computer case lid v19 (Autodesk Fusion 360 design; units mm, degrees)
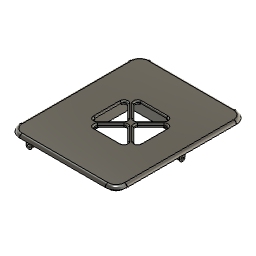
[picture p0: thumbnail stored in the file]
sketch "草图1" plane through (0, 0, 0) normal (0, 0, 1) x axis (1, 0, 0)
  line L1 (-5, 3.05) -> (-5, 81.95)
  line L2 (64.95, -5) -> (3.05, -5)
  line L3 (3.05, -3) -> (64.95, -3)
  line L4 (73, 81.95) -> (73, 3.05)
  line L5 (67.9994, 85) -> (0.0006, 85)
  line L6 (71, 3.05) -> (71, 81.95)
  line L7 (-3, 81.95) -> (-3, 3.05)
  line L8 (3.05, 90) -> (64.95, 90)
  line L9 (3.05, -1) -> (64.95, -1)
  line L10 (69, 3.05) -> (69, 81.95)
  line L11 (67.9994, 83) -> (0.0006, 83)
  line L12 (-1, 81.95) -> (-1, 3.05)
  line L13 (70.75, 3.05) -> (70.75, 81.95)
  line L14 (67.9994, 84.75) -> (0.0006, 84.75)
  line L15 (-2.75, 81.95) -> (-2.75, 3.05)
  line L16 (3.05, -2.75) -> (64.95, -2.75)
  arc A1 centre (0, 3.05) radius 3 clockwise from (-2.9993, 2.9875) to (-3, 3.05)
  arc A2 centre (68, 3.05) radius 3 clockwise from (71, 3.05) to (70.9993, 2.9875)
  arc A3 centre (0, 3.05) radius 5 clockwise from (-4.9995, 2.9792) to (-5, 3.05)
  arc A4 centre (68, 3.05) radius 5 clockwise from (73, 3.05) to (72.9995, 2.9792)
  arc A5 centre (64.95, 0) radius 3 clockwise from (65.0125, -2.9993) to (64.95, -3)
  arc A6 centre (3.05, 0) radius 3 clockwise from (3.05, -3) to (2.9875, -2.9993)
  arc A7 centre (67.9994, 82) radius 3 clockwise from (67.9994, 85) to (70.9993, 82.0125)
  arc A8 centre (64.95, 85) radius 5 clockwise from (64.95, 90) to (65.0208, 89.9995)
  arc A9 centre (65.05, 0.0004) radius 5 clockwise from (65.1333, -4.9989) to (65.0208, -4.9995)
  arc A10 centre (65.05, 84.9996) radius 5 clockwise from (65.0208, 89.9995) to (65.1333, 89.9989)
  arc A11 centre (65.05, 0.0004) radius 3 clockwise from (65.1, -2.9992) to (65.0125, -2.9993)
  arc A12 centre (68, 81.95) radius 5 clockwise from (72.9995, 82.0208) to (73, 81.95)
  arc A13 centre (0.0004, 82.05) radius 5 clockwise from (-4.9995, 82.0208) to (-4.9989, 82.1333)
  arc A14 centre (64.95, 0) radius 5 clockwise from (65.0208, -4.9995) to (64.95, -5)
  arc A15 centre (65, 3) radius 8 clockwise from (72.9989, 2.8667) to (65.1333, -4.9989)
  arc A16 centre (2.95, 0.0004) radius 3 clockwise from (2.9875, -2.9993) to (2.9, -2.9992)
  arc A17 centre (65, 3) radius 6 clockwise from (70.9992, 2.9) to (65.1, -2.9992)
  arc A18 centre (3, 3) radius 8 clockwise from (2.8667, -4.9989) to (-4.9989, 2.8667)
  arc A19 centre (3.05, 0) radius 5 clockwise from (3.05, -5) to (2.9792, -4.9995)
  arc A20 centre (3, 82) radius 8 clockwise from (-4.9989, 82.1333) to (2.8667, 89.9989)
  arc A21 centre (0.0004, 2.95) radius 3 clockwise from (-2.9992, 2.9) to (-2.9993, 2.9875)
  arc A22 centre (2.95, 0.0004) radius 5 clockwise from (2.9792, -4.9995) to (2.8667, -4.9989)
  arc A23 centre (67.9996, 82.05) radius 5 clockwise from (72.9989, 82.1333) to (72.9995, 82.0208)
  arc A24 centre (0.0006, 82) radius 3 clockwise from (-2.9993, 82.0125) to (0.0006, 85)
  arc A25 centre (2.95, 84.9996) radius 5 clockwise from (2.8667, 89.9989) to (2.9792, 89.9995)
  arc A26 centre (0.0004, 2.95) radius 5 clockwise from (-4.9989, 2.8667) to (-4.9995, 2.9792)
  arc A27 centre (3.05, 85) radius 5 clockwise from (2.9792, 89.9995) to (3.05, 90)
  arc A28 centre (68, 81.95) radius 3 clockwise from (70.9993, 82.0125) to (71, 81.95)
  arc A29 centre (65, 82) radius 8 clockwise from (65.1333, 89.9989) to (72.9989, 82.1333)
  arc A30 centre (0, 81.95) radius 5 clockwise from (-5, 81.95) to (-4.9995, 82.0208)
  arc A31 centre (67.9996, 2.95) radius 3 clockwise from (70.9993, 2.9875) to (70.9992, 2.9)
  arc A32 centre (0, 81.95) radius 3 clockwise from (-3, 81.95) to (-2.9993, 82.0125)
  arc A33 centre (67.9996, 2.95) radius 5 clockwise from (72.9995, 2.9792) to (72.9989, 2.8667)
  arc A34 centre (3, 3) radius 6 clockwise from (2.9, -2.9992) to (-2.9992, 2.9)
  arc A35 centre (3.05, 0) radius 1 clockwise from (3.05, -1) to (2.9958, -0.9985)
  arc A36 centre (64.95, 0) radius 1 clockwise from (65.0042, -0.9985) to (64.95, -1)
  arc A37 centre (65.05, 0.0004) radius 1 clockwise from (65.0667, -0.9994) to (65.0042, -0.9985)
  arc A38 centre (65, 3) radius 4 clockwise from (68.9994, 2.9333) to (65.0667, -0.9994)
  arc A39 centre (67.9996, 2.95) radius 1 clockwise from (68.9985, 2.9958) to (68.9994, 2.9333)
  arc A40 centre (68, 3.05) radius 1 clockwise from (69, 3.05) to (68.9985, 2.9958)
  arc A41 centre (68, 81.95) radius 1 clockwise from (68.9993, 81.9875) to (69, 81.95)
  arc A42 centre (67.9994, 82) radius 1 clockwise from (67.9994, 83) to (68.9993, 81.9875)
  arc A43 centre (0.0006, 82) radius 1 clockwise from (-0.9993, 81.9875) to (0.0006, 83)
  arc A44 centre (0, 81.95) radius 1 clockwise from (-1, 81.95) to (-0.9993, 81.9875)
  arc A45 centre (0, 3.05) radius 1 clockwise from (-0.9985, 2.9958) to (-1, 3.05)
  arc A46 centre (0.0004, 2.95) radius 1 clockwise from (-0.9994, 2.9333) to (-0.9985, 2.9958)
  arc A47 centre (3, 3) radius 4 clockwise from (2.9333, -0.9994) to (-0.9994, 2.9333)
  arc A48 centre (2.95, 0.0004) radius 1 clockwise from (2.9958, -0.9985) to (2.9333, -0.9994)
  arc A49 centre (68, 3.05) radius 2.75 clockwise from (70.75, 3.05) to (70.7493, 2.9885)
  arc A50 centre (68, 81.95) radius 2.75 clockwise from (70.7494, 82.0094) to (70.75, 81.95)
  arc A51 centre (67.9994, 82) radius 2.75 clockwise from (67.9994, 84.75) to (70.7494, 82.0094)
  arc A52 centre (0.0006, 82) radius 2.75 clockwise from (-2.7494, 82.0094) to (0.0006, 84.75)
  arc A53 centre (0, 81.95) radius 2.75 clockwise from (-2.75, 81.95) to (-2.7494, 82.0094)
  arc A54 centre (0, 3.05) radius 2.75 clockwise from (-2.7493, 2.9885) to (-2.75, 3.05)
  arc A55 centre (0.0004, 2.95) radius 2.75 clockwise from (-2.7492, 2.9042) to (-2.7493, 2.9885)
  arc A56 centre (3, 3) radius 5.75 clockwise from (2.9042, -2.7492) to (-2.7492, 2.9042)
  arc A57 centre (2.95, 0.0004) radius 2.75 clockwise from (2.9885, -2.7493) to (2.9042, -2.7492)
  arc A58 centre (3.05, 0) radius 2.75 clockwise from (3.05, -2.75) to (2.9885, -2.7493)
  arc A59 centre (64.95, 0) radius 2.75 clockwise from (65.0115, -2.7493) to (64.95, -2.75)
  arc A60 centre (65.05, 0.0004) radius 2.75 clockwise from (65.0958, -2.7492) to (65.0115, -2.7493)
  arc A61 centre (65, 3) radius 5.75 clockwise from (70.7492, 2.9042) to (65.0958, -2.7492)
  arc A62 centre (67.9996, 2.95) radius 2.75 clockwise from (70.7493, 2.9885) to (70.7492, 2.9042)
  dimension "d3" distance L1 L4 = 78
  dimension "d4" distance L2 L8 = 95
  dimension "d5" distance L4 L6 = 2
  dimension "d6" distance L1 L7 = 2
  dimension "d7" distance L2 L3 = 2
  dimension "d8" distance L5 L8 = 5
  dimension "d9" = 2
  dimension "d12" = -0.25
extrude "拉伸1" new body sketch "草图1" profile of A1 A2 A3 A4 A5 A6 A7 L1 A8 A9 A10 A11 A12 A13 L2 L3 A14 A15 L4 A16 A17 A18 A19 A20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 along normal blind 2
extrude "拉伸2" add sketch "草图1" profile of A35 A41 A38 L9 A36 A37 L10 A39 A40 A42 L11 A44 A43 L12 A46 A47 A48 A45 A61 A50 A58 A51 A55 L14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 against normal blind 2
sketch "草图2" plane through (0, 0, 0) normal (0, 0, -1) x axis (1, 0, 0)
  line L1 (-1, -81.95) -> (-1, -3.05)
  line L2 (67.9994, -83) -> (0.0006, -83)
  line L3 (69, -3.05) -> (69, -81.95)
  line L4 (3.05, 1) -> (64.95, 1)
  line L5 (9.5, 2.75) -> (5.5, 2.75)
  line L6 (9.5, -5.25) -> (9.5, 2.75)
  line L7 (5.5, -5.25) -> (9.5, -5.25)
  line L8 (5.5, 2.75) -> (5.5, -5.25)
  line L9 (3.05, 2.75) -> (64.95, 2.75)
  line L10 (-5, -3.05) -> (-5, -81.95)
  line L11 (73.5, -42.5) -> (-5, -42.5)
  line L12 (5.5, -79.75) -> (9.5, -79.75)
  line L13 (5.5, -87.75) -> (5.5, -79.75)
  line L14 (9.5, -87.75) -> (5.5, -87.75)
  line L15 (9.5, -79.75) -> (9.5, -87.75)
  line L16 (9.5, -84.75) -> (5.5, -84.75)
  line L17 (0.0006, -84.75) -> (67.9994, -84.75)
  line L18 (62.75, -47) -> (70.75, -47)
  line L19 (62.75, -43) -> (62.75, -47)
  line L20 (70.75, -43) -> (62.75, -43)
  line L21 (70.75, -47) -> (70.75, -43)
  line L22 (70.75, -81.95) -> (70.75, -3.05)
  line L23 (64.95, 5) -> (3.05, 5)
  arc A1 centre (0, -81.95) radius 1 clockwise from (-0.9993, -81.9875) to (-1, -81.95)
  arc A2 centre (0.0006, -82) radius 1 clockwise from (0.0006, -83) to (-0.9993, -81.9875)
  arc A3 centre (67.9994, -82) radius 1 clockwise from (68.9993, -81.9875) to (67.9994, -83)
  arc A4 centre (68, -81.95) radius 1 clockwise from (69, -81.95) to (68.9993, -81.9875)
  arc A5 centre (68, -3.05) radius 1 clockwise from (68.9985, -2.9958) to (69, -3.05)
  arc A6 centre (67.9996, -2.95) radius 1 clockwise from (68.9994, -2.9333) to (68.9985, -2.9958)
  arc A7 centre (65, -3) radius 4 clockwise from (65.0667, 0.9994) to (68.9994, -2.9333)
  arc A8 centre (65.05, -0.0004) radius 1 clockwise from (65.0042, 0.9985) to (65.0667, 0.9994)
  arc A9 centre (64.95, 0) radius 1 clockwise from (64.95, 1) to (65.0042, 0.9985)
  arc A10 centre (3.05, 0) radius 1 clockwise from (2.9958, 0.9985) to (3.05, 1)
  arc A11 centre (2.95, -0.0004) radius 1 clockwise from (2.9333, 0.9994) to (2.9958, 0.9985)
  arc A12 centre (3, -3) radius 4 clockwise from (-0.9994, -2.9333) to (2.9333, 0.9994)
  arc A13 centre (0.0004, -2.95) radius 1 clockwise from (-0.9985, -2.9958) to (-0.9994, -2.9333)
  arc A14 centre (0, -3.05) radius 1 clockwise from (-1, -3.05) to (-0.9985, -2.9958)
  point P42 (-5, -42.5)
  point P34 (5.5, 2.75)
  point P46 (5.5, -87.75)
  point P35 (9.5, 2.75)
  point P47 (9.5, -87.75)
  point P36 (9.5, -5.25)
  point P44 (9.5, -79.75)
  point P37 (5.5, -5.25)
  point P45 (5.5, -79.75)
  point P48 (5.5, -84.75)
  point P49 (9.5, -84.75)
  point P53 (62.75, -47)
  point P54 (62.75, -43)
  point P55 (70.75, -43)
  horizontal L5
  vertical L6
  horizontal L7
  vertical L8
  collinear L5 L9
  midpoint L10 P42
  perpendicular L10 L11
  symmetric P34 L11 P46
  symmetric P35 L11 P47
  symmetric P36 L11 P44
  symmetric P37 L11 P45
  coincident L13 P48
  coincident L15 P49
  perpendicular L15 L16
  collinear L16 L17
  horizontal L18
  vertical L19
  horizontal L20
  vertical L21
  collinear L21 L22
  dimension "d13" distance P36 P37 = 4
  dimension "d14" distance L8 L10 = 10.5
  dimension "d15" distance P34 P37 = 8
  dimension "d16" distance P53 P54 = 4
  dimension "d17" distance P54 P55 = 8
  dimension "d18" distance L20 L23 = 48
extrude "拉伸3" add sketch "草图2" profile of L2 L3 L4 L5 L6 L7 L8 L9 L12 L13 L15 L16 L17 L18 L19 L20 L21 L22 along normal blind 6
sketch "草图3" plane through (0, 84.75, 0) normal (0, 1, 0) x axis (-1, 0, 0)
  line L1 (-0.0006, -2) -> (-5.5, -2)
  line L2 (-0.0006, 0) -> (-0.0006, -2)
  line L3 (-67.9994, 0) -> (-0.0006, 0)
  line L4 (-67.9994, -2) -> (-67.9994, 0)
  line L5 (-9.5, -2) -> (-67.9994, -2)
  line L6 (-9.5, -6) -> (-9.5, -2)
  line L7 (-5.5, -6) -> (-9.5, -6)
  line L8 (-5.5, -2) -> (-5.5, -6)
  circle C1 centre (-7.5, -4) radius 2
  circle C2 centre (-7.5, -4) radius 0.95
  tangent L7 C1
  tangent L6 C1
  tangent L8 C1
  concentric C1 C2
  dimension "d21" diameter C2 = 1.9
sketch "草图4" plane through (70.75, 0, 0) normal (1, 0, 0) x axis (0, 1, 0)
  line L1 (3.05, 0) -> (81.95, 0)
  line L2 (3.05, -2) -> (3.05, 0)
  line L3 (43, -2) -> (3.05, -2)
  line L4 (43, -6) -> (43, -2)
  line L5 (47, -6) -> (43, -6)
  line L6 (47, -2) -> (47, -6)
  line L7 (81.95, -2) -> (47, -2)
  line L8 (81.95, 0) -> (81.95, -2)
  circle C1 centre (45, -4) radius 2
  circle C2 centre (45, -4) radius 0.95
  tangent L5 C1
  tangent L6 C1
  tangent L4 C1
  concentric C1 C2
  dimension "d22" diameter C2 = 1.9
extrude "拉伸4" cut sketch "草图3" profile of C2 against normal blind 4.75 (magnitude of "-8 mm + 3.25 mm")
extrude "拉伸5" sketch "草图3" profile of C2 blind 8
extrude "拉伸6" cut sketch "草图4" profile of C2 against normal blind 8
sketch "草图5" plane through (0, 0, 2) normal (0, 0, 1) x axis (-1, 0, 0)
  line L1 (-73, -81.95) -> (-73, -3.05)
  line L2 (-3.05, -90) -> (-64.95, -90)
  line L3 (5, -3.05) -> (5, -81.95)
  line L4 (-64.95, 5) -> (-3.05, 5)
  line L5 (-50.429, -58.051) -> (-20.429, -58.051)
  line L6 (-50.429, -28.051) -> (-50.429, -58.051)
  line L7 (-20.429, -28.051) -> (-50.429, -28.051)
  line L8 (-20.429, -58.051) -> (-20.429, -28.051)
  line L9 (-50.429, -28.051) -> (-20.429, -58.051)
  line L10 (-20.429, -28.051) -> (-50.429, -58.051)
  line L11 (-52.929, -60.551) -> (-17.929, -60.551)
  line L12 (-52.929, -25.551) -> (-52.929, -60.551)
  line L13 (-17.929, -25.551) -> (-52.929, -25.551)
  line L14 (-17.929, -60.551) -> (-17.929, -25.551)
  line L15 (-18.929, -28.6723) -> (-49.8077, -59.551)
  line L16 (-21.0503, -26.551) -> (-51.929, -57.4297)
  line L17 (-49.8077, -26.551) -> (-18.929, -57.4297)
  line L18 (-51.929, -28.6723) -> (-21.0503, -59.551)
  line L19 (-18.929, -26.551) -> (-51.929, -26.551)
  line L20 (-18.929, -59.551) -> (-18.929, -26.551)
  line L21 (-51.929, -59.551) -> (-18.929, -59.551)
  line L22 (-51.929, -26.551) -> (-51.929, -59.551)
  arc A1 centre (-67.9996, -2.95) radius 5 clockwise from (-72.9995, -2.9792) to (-72.9989, -2.8667)
  arc A2 centre (-68, -3.05) radius 5 clockwise from (-73, -3.05) to (-72.9995, -2.9792)
  arc A3 centre (-68, -81.95) radius 5 clockwise from (-72.9995, -82.0208) to (-73, -81.95)
  arc A4 centre (-67.9996, -82.05) radius 5 clockwise from (-72.9989, -82.1333) to (-72.9995, -82.0208)
  arc A5 centre (-65, -82) radius 8 clockwise from (-65.1333, -89.9989) to (-72.9989, -82.1333)
  arc A6 centre (-65.05, -84.9996) radius 5 clockwise from (-65.0208, -89.9995) to (-65.1333, -89.9989)
  arc A7 centre (-64.95, -85) radius 5 clockwise from (-64.95, -90) to (-65.0208, -89.9995)
  arc A8 centre (-3.05, -85) radius 5 clockwise from (-2.9792, -89.9995) to (-3.05, -90)
  arc A9 centre (-2.95, -84.9996) radius 5 clockwise from (-2.8667, -89.9989) to (-2.9792, -89.9995)
  arc A10 centre (-3, -82) radius 8 clockwise from (4.9989, -82.1333) to (-2.8667, -89.9989)
  arc A11 centre (-0.0004, -82.05) radius 5 clockwise from (4.9995, -82.0208) to (4.9989, -82.1333)
  arc A12 centre (0, -81.95) radius 5 clockwise from (5, -81.95) to (4.9995, -82.0208)
  arc A13 centre (0, -3.05) radius 5 clockwise from (4.9995, -2.9792) to (5, -3.05)
  arc A14 centre (-0.0004, -2.95) radius 5 clockwise from (4.9989, -2.8667) to (4.9995, -2.9792)
  arc A15 centre (-3, -3) radius 8 clockwise from (-2.8667, 4.9989) to (4.9989, -2.8667)
  arc A16 centre (-2.95, -0.0004) radius 5 clockwise from (-2.9792, 4.9995) to (-2.8667, 4.9989)
  arc A17 centre (-3.05, 0) radius 5 clockwise from (-3.05, 5) to (-2.9792, 4.9995)
  arc A18 centre (-64.95, 0) radius 5 clockwise from (-65.0208, 4.9995) to (-64.95, 5)
  arc A19 centre (-65.05, -0.0004) radius 5 clockwise from (-65.1333, 4.9989) to (-65.0208, 4.9995)
  arc A20 centre (-65, -3) radius 8 clockwise from (-72.9989, -2.8667) to (-65.1333, 4.9989)
  point P56 (-51.929, -57.4297)
  point P54 (-49.8077, -59.551)
  point P57 (-21.0503, -26.551)
  point P55 (-18.929, -28.6723)
  point P61 (-51.929, -28.6723)
  point P59 (-49.8077, -26.551)
  point P60 (-21.0503, -59.551)
  point P58 (-18.929, -57.4297)
  point P46 (-20.429, -58.051)
  point P47 (-50.429, -58.051)
  horizontal L5
  vertical L6
  horizontal L7
  vertical L8
  equal L5 L6
  coincident P56 L22
  coincident P54 L21
  coincident P57 L19
  coincident P55 L20
  coincident P61 L22
  coincident P59 L19
  coincident P60 L21
  coincident P58 L20
  dimension "d30" distance P46 P47 = 30
  dimension "d31" distance L1 L6 = 22.571
  dimension "d32" distance L4 L7 = 33.051
  dimension "d40" = -2.5
  dimension "d83" = 1.5
  dimension "d84" = -1.5
  dimension "d85" = 1.5
  dimension "d86" = -1.5
  dimension "d103" = -1.5
extrude "拉伸13" cut sketch "草图5" profile of L5 L6 L7 L8 L15 L16 L17 L18 L21 L20 L19 L22 against normal blind 2
extrude "拉伸14" sketch "草图5" profile of L11 L12 L14 L13 L21 L20 L19 L22 blind -6
extrude "拉伸15" add of existing geometry blind 2
fillet "圆角12" radius 2
fillet "圆角16" radius 2
fillet "圆角17" radius 1
fillet "圆角1" radius 2
fillet "圆角2" radius 2
fillet "圆角3" radius 1
fillet "圆角4" radius 1
fillet "圆角5" radius 1
fillet "圆角6" radius 2
fillet "圆角14" radius 2
fillet "圆角15" radius 1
